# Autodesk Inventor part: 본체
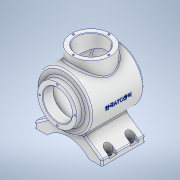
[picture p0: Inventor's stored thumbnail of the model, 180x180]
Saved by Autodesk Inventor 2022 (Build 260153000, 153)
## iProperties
Created: 2023-04
Part Number: 본체
Material: 알루미늄 6061
Document SubType Name: Modeling
Designer: Admin
Mass: 1296.71 g
Surface Area: 1060.44 cm^2
Volume: 480.263 cm^3
Density: 2.7 g/cm^3
Appearance: 알루미늄 - 평지
Author: Admin
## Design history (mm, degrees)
sketch "스케치1"
  geometry: L1 (-62, 0)-(-45.825, 0); L2 (-62, 0)-(-62, 10); L3 (-62, 10)-(-4.874, 50); L4 (-4.874, 50)-(4.874, 50); L5 (4.874, 50)-(62, 10); L6 (62, 10)-(62, 0); L7 (62, 0)-(-45.825, 0); L8 (0, -10)-(0, 60) reference; L9 (-86.8, 0)-(86.8, 0) reference; 1 further point
  constraints: 14 end point, 2 horizontal, 2 perpendicular, 1 point on line, 1 vertical, 2 other
  dimensions: "d0" = 55 deg angle of L6 L5; "d1" = 10 distance from line of L5.end L7; "d3" = 124 distance from line of L5.end L2; "d4" = 50 distance between parallel lines of L9 L4
extrude "돌출1" new body sketch "스케치1" stored distance "d5" = 80; taper "d6" = 0 deg
sketch "스케치2"
  geometry: L1 (-62, 0)-(62, 0) reference; L2 (0, -52.115)-(0, 67.019) reference; L3 (0, 17)-(96.6, 17); L4 (-38.5, 0)-(38.5, 0); A1 r 52.096 centre (0, -35.096) between (38.5, 0) and (-38.5, 0); 1 further point
  constraints: 4 end point, 3 point on circle, 3 point on line, 1 centre point, 1 collinear, 1 horizontal, 1 symmetric about line, 1 tangent
  dimensions: "d7" = 77 distance of L4.end L4.start; "d8" = 17 distance between parallel lines of L1 L3
extrude "돌출2" cut sketch "스케치2" extent not by distance; stored distance "d9" = 0; taper "d10" = 0 deg
sketch "스케치3"
  geometry: L1 (77, 118.354)-(77, -116.879); L2 (0, -40)-(0, 40) reference; L3 (104, 60)-(113, 60); L4 (113, 60)-(113, 48); L5 (113, 48)-(127, 48); L6 (127, 48)-(127, -48.336); L7 (104, 60)-(104, 41); L8 (104, 41)-(120, 41); L9 (0, 40)-(17, 40) reference; L10 (120, 41)-(120, -43.887); L11 (77, -53)-(77, -60); A1 r 113 centre (77, 53) between (77, -60) and (127, -48.336); A2 r 106 centre (77, 53) between (77, -53) and (120, -43.887); 1 further point
  constraints: 18 end point, 4 perpendicular, 4 point on circle, 4 vertical, 2 centre point, 2 point on line, 1 horizontal
  dimensions: "d11" = 77 distance between parallel lines of L2 L1; "d12" = 54 diameter of L7 L1; "d13" = 72 diameter of L4 L1; "d15" = 100 diameter of L6 L1; "d18" = 20 distance between parallel lines of L9 L3; "d21" = 19 distance between parallel lines of L8 L3; "d22" = 113 radius of A1; "d23" = 7 radial gap between concentric circles of A1 A2; "d24" = 108 distance from line of L11.end L5; "d25" = 120 distance from line of L11.end L3; "d26" = 86 diameter of L10 L1
revolve "회전1" sketch "스케치3" stored, may be unused: angle "d27" = 90 deg
sketch "스케치7"
  geometry: L1 (77, 91.081)-(77, -92.811); L2 (0, 40)-(0, -40) reference; L3 (50, -40)-(50, 40) reference; L4 (50, -40)-(34, -40); L5 (34, -40)-(34, 40); L6 (34, 40)-(50, 40); L7 (50, 40)-(50, -40); L8 (39.139, 40)-(39.139, -40) reference; L9 (50, -40)-(39.139, -40) reference; L10 (50, -40)-(50, 40) reference; L11 (39.139, 40)-(50, 40) reference; 1 further point
  constraints: 10 end point, 2 parallel, 1 horizontal, 1 perpendicular, 1 vertical
  dimensions: "d31" = 77 distance between parallel lines of L2 L1; "d32" = 86 diameter of L5 L1
revolve "회전2" sketch "스케치7" stored, may be unused: angle "d33" = 90 deg
node "작업 평면2"
sketch "스케치11"
  geometry: C1 r 27 at (0, 0) reference; 2 further points
  constraints: 1 vertical alignment
  dimensions: "d41" = 32.5 distance of C1.centre point (0, 32.5)
hole "구멍1" sketch "스케치11" at (0, 32.5) diameter "d42" = 3.242; stored, may be unused: countersink angle "d46" = 90 deg, drill point angle "d48" = 118 deg; dims "d43" = 8, "d44" = 4, "d45" = 2, "d47" = 10
sketch "스케치13"
  geometry: L1 (0, 80)-(0, 0) reference; L2 (0, 80)-(23.5, 80) reference; L3 (62, -44)-(62, 124) reference; C1 r 4.5 at (8, 60); C2 r 4.5 at (8, 20); C3 r 4.5 at (116, 60); C4 r 4.5 at (116, 20); 1 further point
  constraints: 4 centre point, 2 symmetric about line, 2 other
  dimensions: "d63" = 8 distance from line of L1 C1.centre; "d64" = 9 diameter of C1; "d65" = 9 diameter of C2 (= d64); "d66" = 40 distance of C2.centre C1.centre; "d67" = 8 distance from line of L1 C2.centre; "d68" = 20 distance from line of L2 C1.centre
extrude "돌출6" cut sketch "스케치13" distance "d69" = 6; taper "d70" = 0 deg
sketch "스케치14"
  geometry: L1 (-8, -60)-(-8, 20) reference; L2 (-8, 7)-(0, 7); L3 (-8, -7)-(0, -7); L4 (-8, 7)-(-8, -7); L5 (-32.8, -20)-(140.8, -20) reference; L6 (54, -104)-(54, 64) reference; L7 (116, -7)-(108, -7); L8 (116, 7)-(108, 7); L9 (116, -60)-(116, 20); L10 (116, 7)-(116, -7); L11 (-8, -33)-(0, -33); L12 (-8, 20)-(-8, -60); L13 (-8, -47)-(-8, -33); L14 (-8, -47)-(0, -47); L15 (116, -33)-(108, -33); L16 (116, -47)-(108, -47); L17 (116, 20)-(116, -60); L18 (116, -47)-(116, -33); C1 r 4.5 at (0, 0) reference; A1 r 7 centre (0, 0) between (0, -7) and (0, 7); A2 r 7 centre (108, 0) between (108, 7) and (108, -7); A3 r 7 centre (0, -40) between (0, -47) and (0, -33); A4 r 7 centre (108, -40) between (108, -33) and (108, -47); 1 further point
  constraints: 30 end point, 21 symmetric about line, 8 point on circle, 8 point on line, 4 centre point, 2 horizontal, 2 tangent, 1 coincident, 1 vertical, 3 other
  dimensions: "d71" = 14 diameter of A1
extrude "돌출7" cut sketch "스케치14" stored distance "d72" = 6; taper "d73" = 0 deg
node "작업 평면3"
sketch "스케치15"
  geometry: L1 (41, 60)-(113, 60) reference; L2 (0, -40)-(0, 40) reference; 2 further points
  constraints: 1 other
  dimensions: "d76" = 77 distance from line of L2 point (77, -2); "d85" = 62 distance from line of point (77, -2) L1
feature "엠보싱1" sketch "스케치15" dims "d0" = 55 deg, "d1" = 10, "d3" = 124, "d4" = 50, "d77" = 0.5, "d78" = 0
chamfer "모따기1" distance "d79" = 1; stored, may be unused: second distance "d80" = 2, angle "d81" = 45 deg
fillet "모깎기1" dims "d82" = 3
fillet "모깎기2" dims "d83" = 3
node "작업 평면4"
sketch "스케치17"
  geometry: L1 (-36, 60)-(36, 60) reference; L2 (0, -84)-(0, 84) reference; C1 r 36 at (0, -2); 1 further point
  constraints: 1 centre point, 1 point on line
  dimensions: "d88" = 62 distance from line of L1 C1.centre; "d89" = 72 diameter of C1
extrude "돌출8" join sketch "스케치17" stored distance "d90" = 10; taper "d91" = 0 deg
sketch "스케치18"
  geometry: C1 r 36 at (0, 0) reference; C2 r 27 at (0, 0); 1 further point
  constraints: 1 centre point, 1 coincident
  dimensions: "d92" = 54 diameter of C2
extrude "돌출9" cut sketch "스케치18" stored distance "d93" = 10; taper "d94" = 0 deg
sketch "스케치19"
  geometry: C1 r 36 at (0, 0) reference; 2 further points
  constraints: 1 vertical alignment
  dimensions: "d95" = 32.5 distance of C1.centre point (0, 32.5)
hole "구멍3" sketch "스케치19" at (0, 32.5) diameter "d96" = 3.242; stored, may be unused: countersink angle "d100" = 90 deg, drill point angle "d102" = 118 deg; dims "d97" = 8, "d98" = 4, "d99" = 2, "d101" = 10
fillet "모깎기3" dims "d106" = 3
chamfer "모따기2" distance "d107" = 1; stored, may be unused: second distance "d108" = 2, angle "d109" = 45 deg
node "솔리드1"
pattern_circular "원형 패턴1" dims angle "d50" = 360 deg
pattern_circular "원형 패턴3" dims angle "d104" = 360 deg
node "투영된 루프2"
feature "A9D066F2-1C7D-4E18-AEED-F7BC21143FA4" dims "d42" = 3.242, "d43" = 8, "d44" = 4, "d45" = 2, "d46" = 90 deg, "d47" = 10, "d48" = 118 deg
other parameters: "d34" = 142, "d74" = 99.25, "d87" = 142
